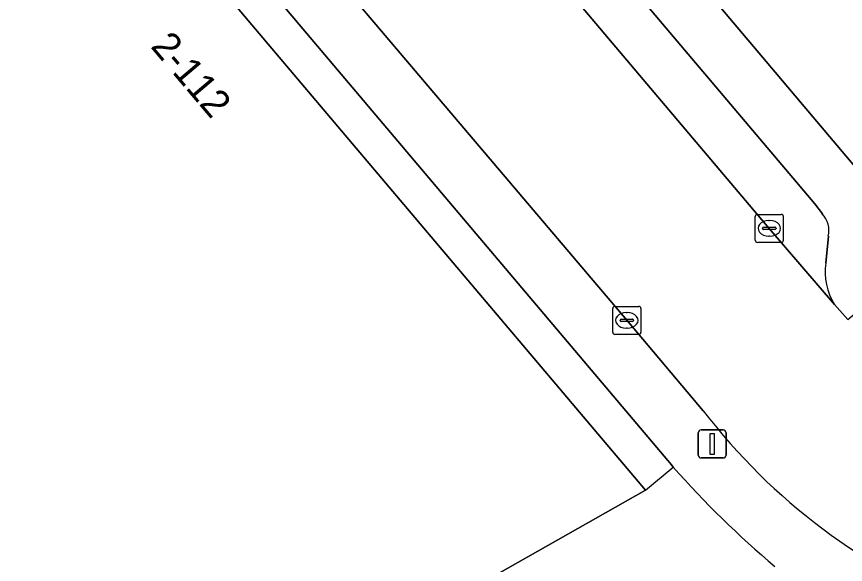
# Model space of a CAD drawing. Extents: x 162172 to 163187, y 382874 to 383685.
# Drawn here: x 162269.36 to 162298.92, y 383133.13 to 383152.67 of the extents above; entities that cross this region are included whole.
import ezdxf

# ---------------------------------------------------------------- set-up
doc = ezdxf.new("R2010")
doc.units = 0
for name, color, linetype in [('IMGEO_Erf', 7, 'Continuous'), ('IMGEO_Hek', 7, 'Continuous'), ('IMGEO_Kolk', 7, 'Continuous'), ('IMGEO_Lichtmast', 7, 'Continuous'), ('IMGEO_Pand', 7, 'Continuous'), ('IMGEO_Pand_nummerreeks', 7, 'Continuous'), ('IMGEO_Parkeervlak_open', 7, 'Continuous'), ('IMGEO_Rijbaan_lokaal_open', 7, 'Continuous'), ('IMGEO_Voetpad_open', 7, 'Continuous')]:
    doc.layers.add(name, color=color, linetype=linetype)

msp = doc.modelspace()

# ---------------------------------------------------------------- linework, layer by layer
at = {"layer": 'IMGEO_Erf'}
msp.add_lwpolyline([(162292.775, 383136.6), (162292.721, 383136.685), (162272.278, 383160.872), (162265.384, 383169.014)], dxfattribs=at)
msp.add_lwpolyline([(162241.583, 383133.932), (162239.407, 383129.914), (162231.246, 383139.566), (162264.665, 383167.841), (162291.787, 383135.773), (162253.016, 383113.808), (162244.709, 383123.649), (162247.341, 383125.137)], close=True, dxfattribs=at)
msp.add_arc((162318.777, 383159.538), 34.673, 221.4177, 229.8117, dxfattribs=at)
at = {"layer": 'IMGEO_Hek'}
msp.add_lwpolyline([(162291.787, 383135.773), (162292.775, 383136.6)], dxfattribs=at)
at = {"layer": 'IMGEO_Kolk'}
for p, q in [((162295.703, 383144.691), (162295.703, 383145.543)), ((162295.778, 383145.617), (162296.63, 383145.617)), ((162296.704, 383145.543), (162296.704, 383144.691)), ((162296.191, 383145.397), (162296.216, 383145.397)), ((162295.962, 383145.111), (162295.962, 383145.123)), ((162296.4, 383145.074), (162296.002, 383145.074)), ((162296.005, 383145.16), (162296.403, 383145.16)), ((162296.446, 383145.123), (162296.446, 383145.111)), ((162296.63, 383144.617), (162295.778, 383144.617)), ((162296.214, 383144.837), (162296.189, 383144.837)), ((162290.621, 383141.409), (162290.621, 383142.261)), ((162290.696, 383142.335), (162291.548, 383142.335)), ((162291.622, 383142.261), (162291.622, 383141.409)), ((162291.109, 383142.115), (162291.134, 383142.115)), ((162290.88, 383141.829), (162290.88, 383141.841)), ((162291.318, 383141.792), (162290.92, 383141.792)), ((162290.923, 383141.878), (162291.321, 383141.878)), ((162291.364, 383141.841), (162291.364, 383141.829)), ((162291.132, 383141.555), (162291.107, 383141.555)), ((162291.548, 383141.335), (162290.696, 383141.335))]:
    msp.add_line(p, q, dxfattribs=at)
for points in [[(162295.703, 383144.691), (162295.703, 383145.543)], [(162295.778, 383145.617), (162296.63, 383145.617)], [(162296.704, 383145.543), (162296.704, 383144.691)], [(162296.63, 383144.617), (162295.778, 383144.617)], [(162290.621, 383141.409), (162290.621, 383142.261)], [(162290.696, 383142.335), (162291.548, 383142.335)], [(162291.622, 383142.261), (162291.622, 383141.409)], [(162291.548, 383141.335), (162290.696, 383141.335)]]:
    msp.add_lwpolyline(points, dxfattribs=at)
for centre, radius, start, end in [((162295.78, 383145.541), 0.0765, 91.552, 178.448), ((162295.78, 383145.541), 0.0765, 91.552, 178.448), ((162296.628, 383145.541), 0.0765, 1.552, 88.448), ((162296.628, 383145.541), 0.0765, 1.552, 88.448), ((162296.002, 383145.12), 0.0403, 85.8775, 175.7526), ((162295.999, 383145.11), 0.0366, 178.938, 274.7102), ((162296.403, 383145.117), 0.043, 264.8664, 352.4533), ((162296.407, 383145.122), 0.0386, 1.7309, 96.639), ((162295.78, 383144.693), 0.0765, 181.552, 268.448), ((162295.78, 383144.693), 0.0765, 181.552, 268.448), ((162296.628, 383144.693), 0.0765, 271.552, 358.448), ((162296.628, 383144.693), 0.0765, 271.552, 358.448), ((162290.698, 383142.259), 0.0765, 91.552, 178.448), ((162290.698, 383142.259), 0.0765, 91.552, 178.448), ((162291.546, 383142.259), 0.0765, 1.552, 88.448), ((162291.546, 383142.259), 0.0765, 1.552, 88.448), ((162290.92, 383141.838), 0.0403, 85.8775, 175.7526), ((162290.917, 383141.828), 0.0366, 178.938, 274.7102), ((162291.321, 383141.835), 0.043, 264.8664, 352.4533), ((162291.325, 383141.84), 0.0386, 1.7309, 96.639), ((162290.698, 383141.411), 0.0765, 181.552, 268.448), ((162290.698, 383141.411), 0.0765, 181.552, 268.448), ((162291.546, 383141.411), 0.0765, 271.552, 358.448), ((162291.546, 383141.411), 0.0765, 271.552, 358.448)]:
    msp.add_arc(centre, radius, start, end, dxfattribs=at)
for centre, major_axis, ratio, start_param, end_param in [((162296.19, 383145.117), (-0.387, 0.002), 0.722429, 4.712389, 7.853982), ((162296.215, 383145.117), (-0.39, 0.002), 0.717154, 1.570796, 4.712389), ((162291.108, 383141.835), (-0.387, 0.002), 0.722429, 4.712389, 7.853982), ((162291.133, 383141.835), (-0.39, 0.002), 0.717154, 1.570796, 4.712389)]:
    msp.add_ellipse(centre, major_axis=major_axis, ratio=ratio, start_param=start_param, end_param=end_param, dxfattribs=at)
at = {"layer": 'IMGEO_Lichtmast'}
for p, q in [((162293.67, 383137.024), (162293.67, 383137.824)), ((162293.67, 383137.824), (162293.67, 383137.024)), ((162293.77, 383137.924), (162294.56, 383137.924)), ((162294.56, 383137.924), (162293.77, 383137.924)), ((162294.66, 383137.824), (162294.66, 383137.024)), ((162294.66, 383137.024), (162294.66, 383137.824)), ((162294.56, 383136.924), (162293.77, 383136.924)), ((162293.77, 383136.924), (162294.56, 383136.924))]:
    msp.add_line(p, q, dxfattribs=at)
msp.add_lwpolyline([(162294.09, 383137.799), (162294.24, 383137.799), (162294.24, 383137.049), (162294.09, 383137.049), (162294.09, 383137.799)], dxfattribs=at)
for centre, start, end in [((162293.77, 383137.824), 90, 180), ((162293.77, 383137.824), 90, 180), ((162294.56, 383137.824), 0, 90), ((162294.56, 383137.824), 360, 90), ((162293.77, 383137.024), 180, 270), ((162293.77, 383137.024), 180, 270), ((162294.56, 383137.024), 270, 0), ((162294.56, 383137.024), 270, 0)]:
    msp.add_arc(centre, 0.1, start, end, dxfattribs=at)
at = {"layer": 'IMGEO_Pand'}
for points in [[(162291.787, 383135.773), (162264.665, 383167.841), (162231.246, 383139.566), (162239.407, 383129.914), (162241.583, 383133.932), (162247.341, 383125.137), (162244.709, 383123.649), (162253.016, 383113.808)], [(162299.171, 383157.692), (162298.744, 383157.331), (162298.518, 383157.598), (162293.888, 383153.688), (162300.554, 383145.796), (162305.184, 383149.712), (162304.962, 383149.985), (162305.323, 383150.29)]]:
    msp.add_lwpolyline(points, close=True, dxfattribs=at)
at = {"layer": 'IMGEO_Parkeervlak_open'}
for points in [[(162271.302, 383174.605), (162272.303, 383173.366), (162272.674, 383172.984), (162285.517, 383157.752), (162296.202, 383145.116), (162298.527, 383142.396)], [(162298.095, 383145.637), (162297.831, 383145.99), (162274.594, 383173.469)], [(162298.221, 383143.878), (162298.309, 383144.838)]]:
    msp.add_lwpolyline(points, dxfattribs=at)
for centre, radius, start, end in [((162297.437, 383145.033), 0.893, 347.4111, 42.5767), ((162300.34, 383143.543), 2.145, 171.0121, 212.3206)]:
    msp.add_arc(centre, radius, start, end, dxfattribs=at)
at = {"layer": 'IMGEO_Rijbaan_lokaal_open'}
for points in [[(162299.002, 383141.868), (162298.527, 383142.396), (162296.202, 383145.116), (162285.517, 383157.752), (162272.674, 383172.984), (162272.303, 383173.366), (162271.302, 383174.605), (162270.945, 383175.04)], [(162266.946, 383170.378), (162267.745, 383169.423), (162268.153, 383168.966), (162275.979, 383159.733), (162280.064, 383154.913), (162281.1, 383153.659), (162291.122, 383141.836), (162293.849, 383138.608)]]:
    msp.add_lwpolyline(points, dxfattribs=at)
msp.add_arc((162311.461, 383152.145), 22.213, 217.546, 248.5501, dxfattribs=at)
at = {"layer": 'IMGEO_Voetpad_open'}
for points in [[(162300.554, 383145.796), (162293.888, 383153.688), (162289.573, 383158.763), (162287.676, 383161.058), (162286.7, 383162.189), (162284.736, 383164.507), (162281.412, 383168.439), (162274.737, 383176.332), (162271.302, 383174.605)], [(162274.594, 383173.469), (162297.831, 383145.99), (162298.095, 383145.637)], [(162268.153, 383168.966), (162267.745, 383169.423), (162266.946, 383170.378), (162265.384, 383169.014), (162272.278, 383160.872), (162292.721, 383136.685), (162292.775, 383136.6)], [(162293.849, 383138.608), (162291.122, 383141.836), (162281.1, 383153.659), (162280.064, 383154.913), (162279.683, 383154.591), (162275.604, 383159.416), (162275.979, 383159.733), (162268.153, 383168.966)], [(162298.309, 383144.838), (162298.221, 383143.878)], [(162298.527, 383142.396), (162299.002, 383141.868), (162299.387, 383142.187)]]:
    msp.add_lwpolyline(points, dxfattribs=at)
for centre, radius, start, end in [((162297.437, 383145.033), 0.893, 347.4111, 42.5767), ((162300.34, 383143.543), 2.145, 171.0121, 212.3206), ((162311.461, 383152.145), 22.213, 217.546, 248.5501), ((162318.777, 383159.538), 34.673, 221.4177, 229.8117)]:
    msp.add_arc(centre, radius, start, end, dxfattribs=at)

# ---------------------------------------------------------------- texts
at = {"layer": 'IMGEO_Pand_nummerreeks'}
msp.add_text('2-112', height=1, rotation=310.2234, dxfattribs=at).set_placement((162274.11, 383151.596))

doc.saveas('drawing.dxf')
